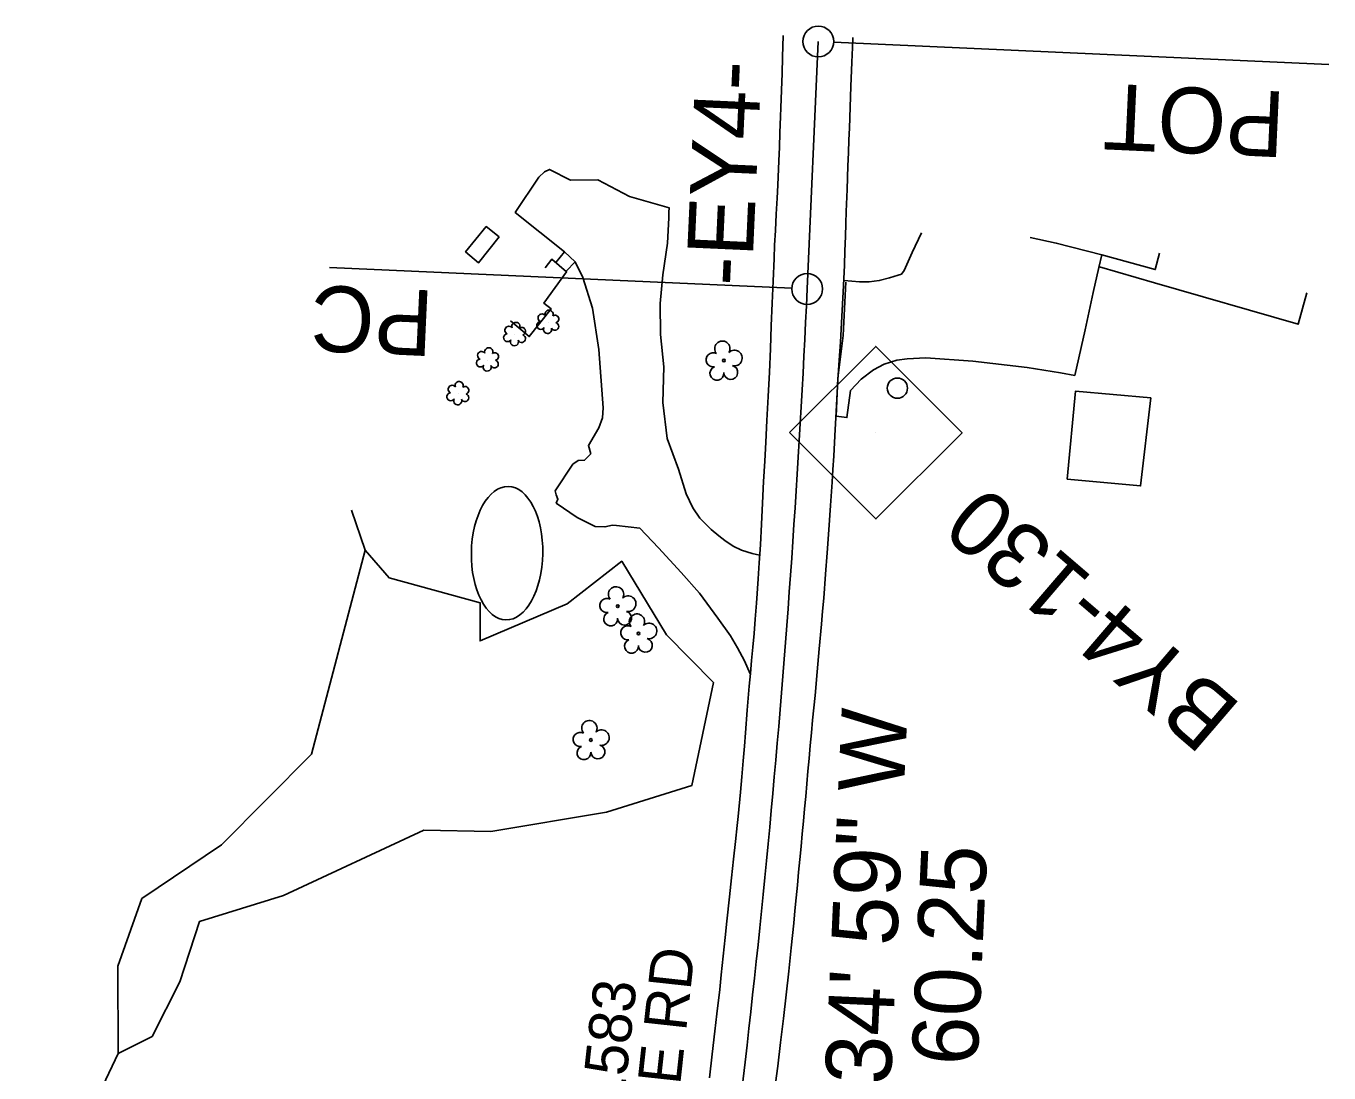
# Model space of a CAD drawing. Extents: x 478596 to 483012, y 490885 to 495165.
# Drawn here: x 480644.3 to 480961.1, y 493451.6 to 493706.2 of the extents above; entities that cross this region are included whole.
import ezdxf

# ---------------------------------------------------------------- set-up
doc = ezdxf.new("R2010")
doc.units = 0
for name, color, linetype in [('CTL Secondary Horizontal and Vertical CELL', 7, 'Continuous'), ('CTL Secondary Horizontal and Vertical Text', 7, 'Continuous'), ('Exist Building Metal Canopy', 7, 'Continuous'), ('Exist Horizontal Alignment', 7, 'Continuous'), ('Exist Horizontal Alignment Direction Label', 7, 'Continuous'), ('Exist Other Culture Area Outline', 7, 'Continuous'), ('Exist Roads Change in Surface', 7, 'Continuous'), ('Exist Roads EOP', 7, 'Continuous'), ('Exist Roads EOP Other', 7, 'Continuous'), ('Exist Roads EOP Text', 7, 'Continuous'), ('Exist Roads Soil', 7, 'Continuous'), ('Exist Utilities Other Pole CELL', 7, 'Continuous'), ('Exist Vegetation Hedge Row', 7, 'Continuous'), ('Exist Vegetation Shrub CELL', 7, 'Continuous'), ('Exist Vegetation Tree CELL', 7, 'Continuous'), ('Exist Vegetation Woods Line', 7, 'Continuous')]:
    doc.layers.add(name, color=color, linetype=linetype)

msp = doc.modelspace()

# ---------------------------------------------------------------- linework, layer by layer
at = {"layer": 'CTL Secondary Horizontal and Vertical CELL'}
msp.add_line((480850.81, 493607.29), (480850.81, 493607.29), dxfattribs=at)
msp.add_lwpolyline([(480829.95, 493607.36), (480850.92, 493628.32), (480871.92, 493607.32), (480850.95, 493586.36)], close=True, dxfattribs=at)
at = {"layer": 'Exist Building Metal Canopy'}
msp.add_lwpolyline([(480917.81, 493615.85), (480915.3, 493594.39), (480897.48, 493596.05), (480899.5, 493617.44), (480917.81, 493615.85)], dxfattribs=at)
at = {"layer": 'Exist Horizontal Alignment'}
for p, q in [((480836.94, 493702.5), (480834.23, 493642.31)), ((480840.69, 493702.33), (480961.1, 493696.9)), ((480830.48, 493642.48), (480718.12, 493647.55))]:
    msp.add_line(p, q, dxfattribs=at)
for centre in [(480836.94, 493702.5), (480834.23, 493642.31)]:
    msp.add_circle(centre, 3.75, dxfattribs=at)
msp.add_arc((478138.27, 493763.94), 2698.7, 351.84313, 357.4169, dxfattribs=at)
at = {"layer": 'Exist Other Culture Area Outline'}
for points in [[(480759.37, 493654.98), (480754.36, 493648.67), (480751.17, 493651.37), (480756.19, 493657.49), (480759.37, 493654.98)], [(480775.26, 493651.32), (480773.09, 493648.72)], [(480919.89, 493651), (480918.86, 493647.02), (480905.86, 493650.59)], [(480762.13, 493634.57), (480766.65, 493630.73), (480771.98, 493637.48), (480770.19, 493638.85), (480775.74, 493646.48), (480772.15, 493649.51), (480770.54, 493647.47)], [(480775.6, 493646.6), (480777.82, 493648.89)], [(480905.33, 493647.69), (480918.71, 493643.81), (480953.64, 493633.7), (480955.75, 493641.37)]]:
    msp.add_lwpolyline(points, dxfattribs=at)
msp.add_ellipse((480761.27, 493578.03), major_axis=(0.27, 16.23), ratio=0.535519, dxfattribs=at)
at = {"layer": 'Exist Roads Change in Surface'}
msp.add_lwpolyline([(480841.31, 493611.38), (480841.67, 493620.57), (480842.95, 493630.97), (480843.62, 493643.99)], dxfattribs=at)
at = {"layer": 'Exist Roads EOP'}
for points in [[(480828.43, 493703.95), (480828.26, 493698.72), (480828.14, 493694.72), (480828, 493690.63), (480827.86, 493686.37), (480827.78, 493684.25), (480827.62, 493680.31), (480827.47, 493676.76), (480827.34, 493673.47), (480827.08, 493667.54), (480826.92, 493664.36), (480826.72, 493660.52), (480826.51, 493656.54), (480826.33, 493652.94), (480826.17, 493649.72), (480825.93, 493644.23), (480825.72, 493638.84), (480825.52, 493633.36), (480825.3, 493627.77), (480825.05, 493622.05), (480824.75, 493616.18), (480824.43, 493610.27), (480824.15, 493605.01), (480823.91, 493600.38), (480823.65, 493595.47), (480823.37, 493590.23), (480823.1, 493585.05), (480822.85, 493580.06), (480822.6, 493575.66), (480822.35, 493571.81), (480821.92, 493565.9), (480821.62, 493562.02), (480821.34, 493558.52), (480821.04, 493555.21), (480820.73, 493551.93), (480820.42, 493548.74), (480820.13, 493545.69), (480819.66, 493539.82), (480819.25, 493534.32), (480818.99, 493531.09), (480818.69, 493527.54), (480818.36, 493523.66), (480818.02, 493519.89), (480817.46, 493513.97), (480817.23, 493511.82), (480816.8, 493507.87), (480816.33, 493503.58), (480815.85, 493499.07), (480815.37, 493494.47), (480814.74, 493488.53), (480814.32, 493484.58), (480813.83, 493479.97), (480813.35, 493475.5), (480812.96, 493471.92), (480812.27, 493465.98), (480811.78, 493461.76), (480811.15, 493456.15), (480810.52, 493450.38)], [(480845.36, 493703.46), (480845.27, 493701.04), (480845.13, 493697.44), (480844.88, 493691.51), (480844.68, 493686.49), (480844.5, 493681.45), (480844.38, 493678.56), (480844.26, 493675.42), (480844.13, 493672.25), (480843.92, 493666.46), (480843.74, 493661.17), (480843.64, 493658.24), (480843.53, 493655.05), (480843.41, 493651.59), (480843.28, 493648.09), (480843.14, 493644.75), (480843, 493641.58), (480842.68, 493635.62), (480842.51, 493632.55), (480842.32, 493629.39), (480842.11, 493626.13), (480841.73, 493620.19), (480841.46, 493615.61), (480841.2, 493610.99), (480841.04, 493608.15), (480840.86, 493604.95), (480840.68, 493601.62), (480840.49, 493598.42), (480840.31, 493595.34), (480839.94, 493589.65), (480839.53, 493583.74), (480839.11, 493578.13), (480838.72, 493572.95), (480838.25, 493567.08), (480837.99, 493563.92), (480837.71, 493560.75), (480837.19, 493554.78), (480836.68, 493549.21), (480836.15, 493543.44), (480835.86, 493540.44), (480835.57, 493537.39), (480835.29, 493534.32), (480835, 493531.23), (480834.72, 493528.12), (480834.43, 493525.01), (480834.15, 493521.92), (480833.87, 493518.87), (480833.59, 493515.84), (480833.31, 493512.81), (480833.03, 493509.75), (480832.74, 493506.66), (480832.44, 493503.54), (480832.14, 493500.41), (480831.85, 493497.29), (480831.55, 493494.18), (480831.26, 493491.07), (480830.97, 493488.01), (480830.37, 493482.06), (480829.77, 493476.33), (480829.14, 493470.59), (480828.49, 493464.82), (480827.79, 493459.04), (480827.07, 493453.25), (480826.31, 493447.36)]]:
    msp.add_lwpolyline(points, dxfattribs=at)
at = {"layer": 'Exist Roads EOP Other'}
for points in [[(480841.31, 493611.38), (480843.9, 493611.03), (480844.76, 493617.6), (480847.37, 493620.39), (480850.34, 493622.62), (480852.99, 493624.03), (480856.01, 493624.97), (480858.53, 493625.31), (480863.09, 493625.51), (480874.53, 493624.77), (480887.7, 493623.19), (480895.79, 493621.92), (480899.28, 493621.27), (480901.83, 493632.38), (480903.74, 493641.45), (480905.18, 493647.54), (480905.86, 493650.59), (480894.78, 493653.44), (480888.49, 493654.83)], [(480843.21, 493644.36), (480846.94, 493644.02), (480849.3, 493644.04), (480851.78, 493644.35), (480854.27, 493645), (480856.34, 493645.66), (480857.17, 493645.93), (480857.82, 493646.79), (480859.78, 493651.19), (480862.07, 493655.95)]]:
    msp.add_lwpolyline(points, dxfattribs=at)
at = {"layer": 'Exist Roads Soil'}
for points in [[(480800.22, 493605.91), (480799.13, 493614.72), (480799.39, 493623.35), (480798.55, 493631.24), (480798.47, 493638.78), (480799.11, 493645.75), (480800.24, 493653.41), (480800.59, 493659.64), (480800.58, 493660.94), (480800.68, 493662.03), (480791.07, 493664.81), (480783.34, 493668.85), (480776.68, 493668.73), (480771.58, 493671.39), (480770.38, 493670.8), (480768.97, 493669.51), (480763.25, 493660.93), (480775.26, 493651.32), (480777.82, 493648.89), (480779.66, 493645.06), (480782.01, 493637.64), (480783.61, 493627.6), (480784.64, 493613.36), (480784.49, 493610.96), (480783.61, 493608.51), (480781.03, 493604.22), (480781.61, 493602.17), (480780.11, 493600.65), (480778.52, 493600.61), (480777.26, 493599.67), (480772.96, 493593.23), (480773.18, 493592.2), (480773.62, 493591.13), (480773.23, 493590.21), (480778.35, 493586.68), (480782.68, 493584.52), (480785.06, 493584.43), (480786.92, 493584.83), (480787.84, 493584.78), (480793.57, 493584.12)], [(480822.64, 493577.57), (480820.83, 493577.95), (480818.27, 493578.79), (480816.28, 493579.7), (480814.19, 493581.14), (480812.76, 493582.24), (480810.92, 493583.78), (480808.14, 493586.51), (480806.47, 493589.08), (480804.8, 493592.45), (480802.91, 493598.43), (480800.22, 493605.91)], [(480820.35, 493548.72), (480818.97, 493551.87), (480817.3, 493555.02), (480815.56, 493557.95), (480812.53, 493562.19), (480808.08, 493568.31), (480803.59, 493573.33), (480798.06, 493579.3), (480793.57, 493584.12)]]:
    msp.add_lwpolyline(points, dxfattribs=at)
at = {"layer": 'Exist Utilities Other Pole CELL'}
msp.add_circle((480856.17, 493618.18), 2.46, dxfattribs=at)
at = {"layer": 'Exist Vegetation Hedge Row'}
msp.add_lwpolyline([(480726.76, 493578.77), (480732.56, 493572.01), (480754.74, 493565.93), (480754.71, 493556.7), (480775.88, 493565.67), (480789.16, 493576.06), (480800.04, 493558.18), (480811.47, 493546.55), (480806.16, 493521.49), (480785.45, 493515.04), (480757.32, 493510.35), (480741.06, 493510.67), (480706.88, 493494.74), (480686.46, 493488.48), (480681.74, 493473.78), (480674.94, 493460.45), (480666.71, 493456.31)], dxfattribs=at)
at = {"layer": 'Exist Vegetation Shrub CELL'}
for p, q in [((480771.25, 493634.12), (480771.25, 493634.12)), ((480763.18, 493631.15), (480763.18, 493631.15)), ((480756.57, 493624.99), (480756.57, 493624.99)), ((480749.39, 493616.78), (480749.39, 493616.78))]:
    msp.add_line(p, q, dxfattribs=at)
for centre, radius, start, end in [((480763.41, 493633.19), 0.99, 334.8391, 200.4717), ((480769.45, 493633.42), 0.955, 95.1099, 327.9534), ((480769.76, 493635.25), 0.968, 35.8908, 245.4216), ((480771.47, 493636.16), 0.99, 334.8391, 200.4717), ((480772.88, 493633.19), 0.937, 204.9913, 73.4601), ((480772.92, 493634.99), 0.929, 284.4567, 126.0861), ((480761.38, 493630.44), 0.955, 95.1099, 327.9534), ((480761.7, 493632.27), 0.968, 35.8908, 245.4216), ((480764.82, 493630.22), 0.937, 204.9913, 73.4601), ((480764.85, 493632.01), 0.929, 284.4567, 126.0861), ((480771.12, 493632.44), 0.984, 151.2797, 21.387), ((480756.8, 493627.03), 0.99, 334.8391, 200.4717), ((480763.05, 493629.46), 0.984, 151.2797, 21.387), ((480754.77, 493624.29), 0.955, 95.1099, 327.9534), ((480755.08, 493626.12), 0.968, 35.8908, 245.4216), ((480758.2, 493624.06), 0.937, 204.9913, 73.4601), ((480758.24, 493625.86), 0.929, 284.4567, 126.0861), ((480756.44, 493623.31), 0.984, 151.2797, 21.387), ((480747.91, 493617.9), 0.968, 35.8908, 245.4216), ((480749.62, 493618.82), 0.99, 334.8391, 200.4717), ((480751.06, 493617.64), 0.929, 284.4567, 126.0861), ((480747.59, 493616.07), 0.955, 95.1099, 327.9534), ((480749.26, 493615.09), 0.984, 151.2797, 21.387), ((480751.03, 493615.85), 0.937, 204.9913, 73.4601)]:
    msp.add_arc(centre, radius, start, end, dxfattribs=at)
at = {"layer": 'Exist Vegetation Tree CELL'}
for p, q in [((480813.99, 493624.9), (480813.99, 493624.9)), ((480788.16, 493565.14), (480788.16, 493565.14)), ((480793.23, 493558.52), (480793.23, 493558.52)), ((480781.66, 493532.59), (480781.66, 493532.59))]:
    msp.add_line(p, q, dxfattribs=at)
for centre in [(480813.99, 493624.9), (480788.16, 493565.14), (480793.23, 493558.52), (480781.66, 493532.59)]:
    msp.add_circle(centre, 0.326, dxfattribs=at)
for centre, radius, start, end in [((480813.61, 493627.78), 1.86, 330.1651, 219.7134), ((480811.39, 493625.06), 1.73, 62.6636, 279.3457), ((480816.54, 493625.49), 1.9, 257.1011, 134.1999), ((480812.29, 493621.78), 1.69, 111.5671, 6.231), ((480815.66, 493622.01), 1.7, 181.2822, 74.56), ((480787.77, 493568.01), 1.86, 330.1651, 219.7134), ((480790.71, 493565.73), 1.9, 257.1011, 134.1999), ((480785.55, 493565.29), 1.73, 62.6636, 279.3457), ((480786.45, 493562.02), 1.69, 111.5671, 6.231), ((480789.83, 493562.24), 1.7, 181.2822, 74.56), ((480792.85, 493561.39), 1.86, 330.1651, 219.7134), ((480790.63, 493558.68), 1.73, 62.6636, 279.3457), ((480795.78, 493559.11), 1.9, 257.1011, 134.1999), ((480791.53, 493555.4), 1.69, 111.5671, 6.231), ((480794.9, 493555.62), 1.7, 181.2822, 74.56), ((480781.28, 493535.46), 1.86, 330.1651, 219.7134), ((480779.06, 493532.74), 1.73, 62.6636, 279.3457), ((480784.21, 493533.18), 1.9, 257.1011, 134.1999), ((480779.96, 493529.47), 1.69, 111.5671, 6.231), ((480783.34, 493529.69), 1.7, 181.2822, 74.56)]:
    msp.add_arc(centre, radius, start, end, dxfattribs=at)
at = {"layer": 'Exist Vegetation Woods Line'}
msp.add_lwpolyline([(480723.48, 493588.47), (480726.76, 493578.77), (480713.73, 493529.15), (480691.84, 493507.12), (480672.5, 493494.03), (480666.66, 493477.54), (480666.71, 493456.31), (480644.31, 493409.14)], dxfattribs=at)

# ---------------------------------------------------------------- texts
at = {"layer": 'CTL Secondary Horizontal and Vertical Text'}
msp.add_text('BY4-130', height=16, rotation=139.3796, dxfattribs=at).set_placement((480940.23, 493540.84))
at = {"layer": 'Exist Horizontal Alignment'}
for s, p in [('POT', (480950.7, 493690.27)), ('PC', (480743.66, 493641.9))]:
    msp.add_text(s, height=16, rotation=177.4169, dxfattribs=at).set_placement(p)
at = {"layer": 'Exist Horizontal Alignment Direction Label'}
for s, p in [('-EY4-', (480820.71, 493642.8)), ('S 2%%d 34\' 59" W', (480852.42, 493401.97)), ('60.25', (480875.6, 493453.18))]:
    msp.add_text(s, height=16, rotation=87.4169, dxfattribs=at).set_placement(p)
at = {"layer": 'Exist Roads EOP Text'}
for s, p in [('LANCE RD', (480799.33, 493411.63)), ('SR 1583', (480786.96, 493419.86))]:
    msp.add_text(s, height=10.4, rotation=83.7768, dxfattribs=at).set_placement(p)

doc.saveas('drawing.dxf')
